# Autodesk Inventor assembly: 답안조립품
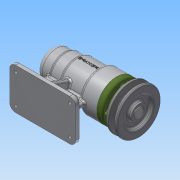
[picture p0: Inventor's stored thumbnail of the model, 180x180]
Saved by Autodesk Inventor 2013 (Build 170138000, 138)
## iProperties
Created: 2016-06
Part Number: 답안조립품
Document SubType Name: Assembly
Designer: Administrator
Author: Administrator
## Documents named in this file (12)
- C:\Users\Administrator\Desktop\460608V1022\답안조립품.iam
- C:\Users\Administrator\Desktop\460608V1022\본체.ipt
- C:\Users\Administrator\Desktop\460608V1022\V벨트풀리.ipt
- C:\Users\Administrator\Desktop\460608V1022\멈춤나사 M3x8.ipt
- C:\Users\Administrator\Desktop\460608V1022\베어링 6004.ipt
- C:\Users\Administrator\Desktop\460608V1022\베어링 51202.ipt
- C:\Users\Administrator\Desktop\460608V1022\볼트 M4 x 12.ipt
- C:\Users\Administrator\Desktop\460608V1022\어댑터슬리브.ipt
- C:\Users\Administrator\Desktop\460608V1022\오일 실.ipt
- C:\Users\Administrator\Desktop\460608V1022\축.ipt
- C:\Users\Administrator\Desktop\460608V1022\커버.ipt
- C:\Users\Administrator\Desktop\460608V1022\키 5 x 5 x 16.ipt
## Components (2 placed, 2 different names)
1. V벨트풀리:1
2. ISO 4762 M4 x 12:1
